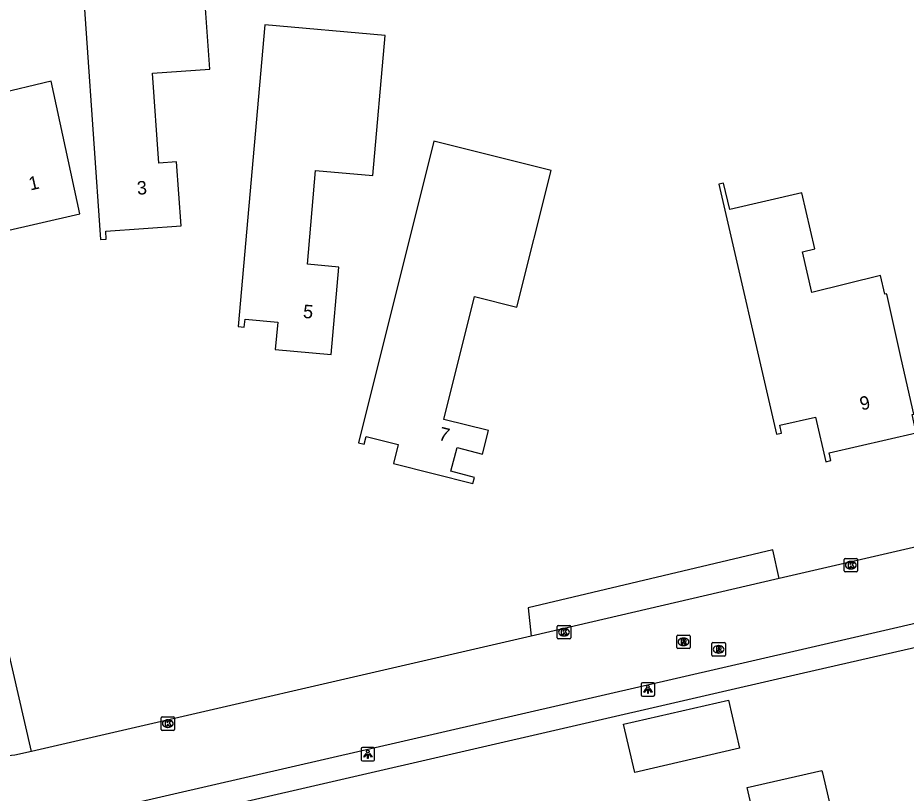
# Model space of a CAD drawing. Extents: x 156414 to 157775, y 382335 to 383765.
# Drawn here: x 156643.8 to 156709.9, y 383066 to 383123.7 of the extents above; entities that cross this region are included whole.
import ezdxf

# ---------------------------------------------------------------- set-up
doc = ezdxf.new("R2010")
doc.units = 0
for name, color, linetype in [('IMGEO_Kolk', 7, 'Continuous'), ('IMGEO_Lichtpunt', 7, 'Continuous'), ('IMGEO_Pand', 7, 'Continuous'), ('IMGEO_Pand_nummerreeks', 7, 'Continuous'), ('IMGEO_Parkeervlak_halfverhard', 7, 'Continuous'), ('IMGEO_Rijbaan_lokaal_gesloten', 7, 'Continuous'), ('IMGEO_Rioolput', 7, 'Continuous'), ('IMGEO_Voetpad_open', 7, 'Continuous')]:
    doc.layers.add(name, color=color, linetype=linetype)

msp = doc.modelspace()

# ---------------------------------------------------------------- linework, layer by layer
at = {"layer": 'IMGEO_Kolk'}
for p, q in [((156705.334, 383083.476), (156706.186, 383083.476)), ((156705.259, 383082.55), (156705.259, 383083.402)), ((156705.747, 383083.256), (156705.772, 383083.256)), ((156706.26, 383083.402), (156706.26, 383082.55)), ((156706.186, 383082.476), (156705.334, 383082.476)), ((156705.77, 383082.696), (156705.745, 383082.696)), ((156683.933, 383077.575), (156683.933, 383078.427)), ((156684.008, 383078.501), (156684.86, 383078.501)), ((156684.421, 383078.281), (156684.446, 383078.281)), ((156684.934, 383078.427), (156684.934, 383077.575)), ((156684.444, 383077.721), (156684.419, 383077.721)), ((156684.86, 383077.501), (156684.008, 383077.501)), ((156654.49, 383070.767), (156654.49, 383071.619)), ((156654.565, 383071.693), (156655.417, 383071.693)), ((156655.491, 383071.619), (156655.491, 383070.767)), ((156655.001, 383070.913), (156654.976, 383070.913)), ((156654.978, 383071.473), (156655.003, 383071.473)), ((156655.417, 383070.693), (156654.565, 383070.693))]:
    msp.add_line(p, q, dxfattribs=at)
for points in [[(156705.334, 383083.476), (156706.186, 383083.476)], [(156705.259, 383082.55), (156705.259, 383083.402)], [(156705.58, 383083.176), (156705.703, 383083.176), (156705.703, 383083.025), (156705.833, 383083.176), (156705.997, 383083.176), (156705.851, 383083.025), (156706.004, 383082.776), (156705.852, 383082.776), (156705.767, 383082.94), (156705.703, 383082.873), (156705.703, 383082.776), (156705.58, 383082.776), (156705.58, 383083.176)], [(156706.26, 383083.402), (156706.26, 383082.55)], [(156706.186, 383082.476), (156705.334, 383082.476)], [(156683.933, 383077.575), (156683.933, 383078.427)], [(156684.008, 383078.501), (156684.86, 383078.501)], [(156684.254, 383078.201), (156684.377, 383078.201), (156684.377, 383078.05), (156684.507, 383078.201), (156684.671, 383078.201), (156684.525, 383078.05), (156684.678, 383077.801), (156684.526, 383077.801), (156684.441, 383077.965), (156684.377, 383077.898), (156684.377, 383077.801), (156684.254, 383077.801), (156684.254, 383078.201)], [(156684.934, 383078.427), (156684.934, 383077.575)], [(156684.86, 383077.501), (156684.008, 383077.501)], [(156654.49, 383070.767), (156654.49, 383071.619)], [(156654.565, 383071.693), (156655.417, 383071.693)], [(156655.491, 383071.619), (156655.491, 383070.767)], [(156654.811, 383071.393), (156654.934, 383071.393), (156654.934, 383071.242), (156655.064, 383071.393), (156655.228, 383071.393), (156655.082, 383071.242), (156655.235, 383070.993), (156655.083, 383070.993), (156654.998, 383071.157), (156654.934, 383071.09), (156654.934, 383070.993), (156654.811, 383070.993), (156654.811, 383071.393)], [(156655.417, 383070.693), (156654.565, 383070.693)]]:
    msp.add_lwpolyline(points, dxfattribs=at)
for centre, start, end in [((156705.336, 383083.4), 91.55205, 178.44795), ((156705.336, 383083.4), 91.55205, 178.44795), ((156706.184, 383083.4), 1.55205, 88.44795), ((156706.184, 383083.4), 1.55205, 88.44795), ((156705.336, 383082.552), 181.55205, 268.44795), ((156705.336, 383082.552), 181.55205, 268.44795), ((156706.184, 383082.552), 271.55205, 358.44795), ((156706.184, 383082.552), 271.55205, 358.44795), ((156684.01, 383078.425), 91.55205, 178.44795), ((156684.01, 383078.425), 91.55205, 178.44795), ((156684.858, 383078.425), 1.55205, 88.44795), ((156684.858, 383078.425), 1.55205, 88.44795), ((156684.01, 383077.577), 181.55205, 268.44795), ((156684.01, 383077.577), 181.55205, 268.44795), ((156684.858, 383077.577), 271.55205, 358.44795), ((156684.858, 383077.577), 271.55205, 358.44795), ((156654.567, 383071.617), 91.55205, 178.44795), ((156654.567, 383071.617), 91.55205, 178.44795), ((156655.415, 383071.617), 1.55205, 88.44795), ((156655.415, 383071.617), 1.55205, 88.44795), ((156654.567, 383070.769), 181.55205, 268.44795), ((156654.567, 383070.769), 181.55205, 268.44795), ((156655.415, 383070.769), 271.55205, 358.44795), ((156655.415, 383070.769), 271.55205, 358.44795)]:
    msp.add_arc(centre, 0.0765, start, end, dxfattribs=at)
for centre, major_axis, ratio, start_param, end_param in [((156705.746, 383082.976), (-0.387, 0.002), 0.722429, 4.712389, 7.853982), ((156705.771, 383082.976), (-0.39, 0.002), 0.717154, 1.570796, 4.712389), ((156684.42, 383078.001), (-0.387, 0.002), 0.722429, 4.712389, 7.853982), ((156684.445, 383078.001), (-0.39, 0.002), 0.717154, 1.570796, 4.712389), ((156654.977, 383071.193), (-0.387, 0.002), 0.722429, 4.712389, 7.853982), ((156655.002, 383071.193), (-0.39, 0.002), 0.717154, 1.570796, 4.712389)]:
    msp.add_ellipse(centre, major_axis=major_axis, ratio=ratio, start_param=start_param, end_param=end_param, dxfattribs=at)
at = {"layer": 'IMGEO_Lichtpunt'}
for p, q in [((156691.084, 383074.226), (156690.276, 383074.226)), ((156691.084, 383074.226), (156690.276, 383074.226)), ((156690.182, 383074.131), (156690.182, 383073.324)), ((156690.182, 383074.131), (156690.182, 383073.324)), ((156691.178, 383073.324), (156691.178, 383074.131)), ((156691.178, 383073.324), (156691.178, 383074.131)), ((156690.276, 383073.23), (156691.084, 383073.23)), ((156690.276, 383073.23), (156691.084, 383073.23)), ((156669.364, 383069.317), (156669.364, 383068.51)), ((156669.364, 383069.317), (156669.364, 383068.51)), ((156670.266, 383069.412), (156669.458, 383069.412)), ((156670.266, 383069.412), (156669.458, 383069.412)), ((156670.36, 383068.51), (156670.36, 383069.317)), ((156670.36, 383068.51), (156670.36, 383069.317)), ((156669.458, 383068.416), (156670.266, 383068.416)), ((156669.458, 383068.416), (156670.266, 383068.416))]:
    msp.add_line(p, q, dxfattribs=at)
for points in [[(156690.556, 383073.795), (156690.595, 383073.767), (156690.407, 383073.505), (156690.369, 383073.532), (156690.556, 383073.795)], [(156690.658, 383073.747), (156690.705, 383073.747), (156690.705, 383073.425), (156690.658, 383073.425), (156690.658, 383073.747)], [(156690.768, 383073.767), (156690.806, 383073.794), (156690.993, 383073.532), (156690.954, 383073.504), (156690.768, 383073.767)], [(156669.738, 383068.981), (156669.777, 383068.953), (156669.589, 383068.691), (156669.551, 383068.718), (156669.738, 383068.981)], [(156669.84, 383068.933), (156669.887, 383068.933), (156669.887, 383068.611), (156669.84, 383068.611), (156669.84, 383068.933)], [(156669.95, 383068.953), (156669.988, 383068.98), (156670.175, 383068.718), (156670.136, 383068.69), (156669.95, 383068.953)]]:
    msp.add_lwpolyline(points, dxfattribs=at)
for centre in [(156690.681, 383073.929), (156669.863, 383069.115)]:
    msp.add_circle(centre, 0.0994, dxfattribs=at)
for centre, start, end in [((156690.276, 383074.131), 90, 180), ((156690.276, 383074.131), 90, 180), ((156691.084, 383074.131), 0, 90), ((156691.084, 383074.131), 0, 90), ((156690.276, 383073.324), 180, 270), ((156690.276, 383073.324), 180, 270), ((156691.084, 383073.324), 270, 0), ((156691.084, 383073.324), 270, 360), ((156669.458, 383069.317), 90, 180), ((156669.458, 383069.317), 90, 180), ((156670.266, 383069.317), 0, 90), ((156670.266, 383069.317), 0, 90), ((156669.458, 383068.51), 180, 270), ((156669.458, 383068.51), 180, 270), ((156670.266, 383068.51), 270, 0), ((156670.266, 383068.51), 270, 360)]:
    msp.add_arc(centre, 0.0946, start, end, dxfattribs=at)
at = {"layer": 'IMGEO_Pand'}
for points in [[(156642.53, 383107.745), (156648.455, 383109.102), (156646.309, 383118.979), (156642.145, 383117.991), (156640.536, 383124.773), (156644.7, 383125.761), (156642.276, 383135.977), (156633.494, 383133.894), (156639.379, 383108.522), (156639.808, 383108.61), (156639.688, 383109.197), (156642.07, 383109.742), (156642.53, 383107.745)], [(156655.97, 383108.231), (156655.639, 383112.983), (156654.312, 383112.891), (156653.845, 383119.584), (156658.105, 383119.882), (156657.377, 383130.306), (156648.432, 383129.682), (156649.988, 383107.211), (156650.412, 383107.235), (156650.377, 383107.834), (156655.97, 383108.231)], [(156667.131, 383098.658), (156667.7, 383105.147), (156665.361, 383105.374), (156665.97, 383112.327), (156670.238, 383111.957), (156671.14, 383122.377), (156662.195, 383123.17), (156660.227, 383100.743), (156660.658, 383100.684), (156660.739, 383101.279), (156663.154, 383101.064), (156662.972, 383099.03), (156667.131, 383098.658)], [(156677.67, 383089.063), (156677.789, 383089.499), (156676.034, 383089.979), (156676.494, 383091.736), (156678.388, 383091.234), (156678.825, 383092.996), (156675.501, 383093.825), (156677.779, 383102.955), (156680.932, 383102.168), (156683.481, 383112.335), (156674.761, 383114.516), (156669.16, 383092.072), (156669.582, 383091.968), (156669.724, 383092.551), (156672.119, 383091.95), (156671.766, 383090.539), (156677.67, 383089.063)], [(156709.503, 383098.344), (156708.449, 383103.028), (156708.413, 383103.174), (156708.296, 383103.145), (156707.953, 383104.533), (156702.857, 383103.273), (156702.16, 383106.294), (156703.076, 383106.505), (156702.116, 383110.671), (156696.77, 383109.433), (156696.302, 383111.384), (156695.95, 383111.311), (156700.223, 383092.713), (156700.601, 383092.796), (156700.472, 383093.382), (156703.125, 383093.982), (156703.898, 383090.668), (156704.271, 383090.754), (156704.137, 383091.339), (156710.627, 383092.83), (156710.315, 383094.185), (156710.432, 383094.212), (156709.503, 383098.344)], [(156689.692, 383067.547), (156688.86, 383071.148), (156696.654, 383072.935), (156697.494, 383069.356), (156689.692, 383067.547)], [(156702.019, 383054.701), (156696.71, 383056.789), (156698.974, 383062.447), (156698.06, 383066.446), (156703.613, 383067.714), (156703.653, 383067.543), (156704.948, 383061.996), (156702.019, 383054.701)]]:
    msp.add_lwpolyline(points, dxfattribs=at)
at = {"layer": 'IMGEO_Parkeervlak_halfverhard'}
msp.add_lwpolyline([(156700.442, 383081.982), (156699.964, 383084.108), (156681.774, 383079.815), (156681.985, 383077.701)], dxfattribs=at)
at = {"layer": 'IMGEO_Rijbaan_lokaal_gesloten'}
for points in [[(156646.397, 383063.893), (156701.856, 383076.667), (156794.235, 383098.006), (156794.644, 383096.091)], [(156754.754, 383094.533), (156700.442, 383081.982)], [(156700.442, 383081.982), (156681.985, 383077.701)], [(156681.985, 383077.701), (156644.854, 383069.113)], [(156644.854, 383069.113), (156643.605, 383068.842), (156642.876, 383068.782)]]:
    msp.add_lwpolyline(points, dxfattribs=at)
at = {"layer": 'IMGEO_Rioolput'}
for p, q in [((156692.822, 383076.852), (156692.822, 383077.704)), ((156692.897, 383077.778), (156693.749, 383077.778)), ((156693.31, 383077.558), (156693.335, 383077.558)), ((156693.823, 383077.704), (156693.823, 383076.852)), ((156693.333, 383076.998), (156693.308, 383076.998)), ((156695.43, 383076.293), (156695.43, 383077.145)), ((156695.505, 383077.219), (156696.357, 383077.219)), ((156695.918, 383076.999), (156695.943, 383076.999)), ((156696.431, 383077.145), (156696.431, 383076.293)), ((156693.749, 383076.778), (156692.897, 383076.778)), ((156696.357, 383076.219), (156695.505, 383076.219)), ((156695.941, 383076.439), (156695.916, 383076.439))]:
    msp.add_line(p, q, dxfattribs=at)
for points in [[(156692.822, 383076.852), (156692.822, 383077.704)], [(156692.897, 383077.778), (156693.749, 383077.778)], [(156693.823, 383077.704), (156693.823, 383076.852)], [(156693.411, 383077.476), (156693.159, 383077.478), (156693.159, 383077.078)], [(156693.159, 383077.078), (156693.283, 383077.078), (156693.283, 383077.24), (156693.294, 383077.24)], [(156693.337, 383077.397), (156693.283, 383077.397), (156693.283, 383077.316)], [(156693.283, 383077.316), (156693.335, 383077.316)], [(156693.341, 383077.211), (156693.412, 383077.078), (156693.552, 383077.078), (156693.487, 383077.204)], [(156695.43, 383076.293), (156695.43, 383077.145)], [(156695.505, 383077.219), (156696.357, 383077.219)], [(156696.019, 383076.917), (156695.767, 383076.919), (156695.767, 383076.519)], [(156696.431, 383077.145), (156696.431, 383076.293)], [(156693.749, 383076.778), (156692.897, 383076.778)], [(156696.357, 383076.219), (156695.505, 383076.219)], [(156695.767, 383076.519), (156695.891, 383076.519), (156695.891, 383076.681), (156695.902, 383076.681)], [(156695.945, 383076.838), (156695.891, 383076.838), (156695.891, 383076.757)], [(156695.891, 383076.757), (156695.943, 383076.757)], [(156695.949, 383076.652), (156696.02, 383076.519), (156696.16, 383076.519), (156696.095, 383076.645)]]:
    msp.add_lwpolyline(points, dxfattribs=at)
for centre, radius, start, end in [((156692.899, 383077.702), 0.0765, 91.55205, 178.44795), ((156692.899, 383077.702), 0.0765, 91.55205, 178.44795), ((156693.747, 383077.702), 0.0765, 1.55205, 88.44795), ((156693.747, 383077.702), 0.0765, 1.55205, 88.44795), ((156692.899, 383076.854), 0.0765, 181.55205, 268.44795), ((156692.899, 383076.854), 0.0765, 181.55205, 268.44795), ((156693.293, 383077.187), 0.0533, 26.02933, 88.69889), ((156693.319, 383077.505), 0.19, 274.7715, 282.96867), ((156693.343, 383077.301), 0.0964, 77.00612, 93.18647), ((156693.357, 383077.358), 0.0378, 276.66336, 79.67722), ((156693.41, 383077.366), 0.109, 350.36119, 89.41601), ((156693.408, 383077.366), 0.112, 277.58423, 350.98172), ((156693.392, 383077.151), 0.108, 29.51342, 73.79051), ((156693.747, 383076.854), 0.0765, 271.55205, 358.44795), ((156693.747, 383076.854), 0.0765, 271.55205, 358.44795), ((156695.507, 383077.143), 0.0765, 91.55205, 178.44795), ((156695.507, 383077.143), 0.0765, 91.55205, 178.44795), ((156696.018, 383076.807), 0.109, 350.36119, 89.41601), ((156696.355, 383077.143), 0.0765, 1.55205, 88.44795), ((156696.355, 383077.143), 0.0765, 1.55205, 88.44795), ((156695.507, 383076.295), 0.0765, 181.55205, 268.44795), ((156695.507, 383076.295), 0.0765, 181.55205, 268.44795), ((156695.901, 383076.628), 0.0533, 26.02933, 88.69889), ((156695.927, 383076.946), 0.19, 274.7715, 282.96867), ((156695.951, 383076.742), 0.0964, 77.00612, 93.18647), ((156695.965, 383076.799), 0.0378, 276.66336, 79.67722), ((156696.016, 383076.807), 0.112, 277.58423, 350.98172), ((156696, 383076.592), 0.108, 29.51342, 73.79051), ((156696.355, 383076.295), 0.0765, 271.55205, 358.44795), ((156696.355, 383076.295), 0.0765, 271.55205, 358.44795)]:
    msp.add_arc(centre, radius, start, end, dxfattribs=at)
for centre, major_axis, ratio, start_param, end_param in [((156693.309, 383077.278), (-0.387, 0.002), 0.722429, 4.712389, 7.853982), ((156693.334, 383077.278), (-0.39, 0.002), 0.717154, 1.570796, 4.712389), ((156695.917, 383076.719), (-0.387, 0.002), 0.722429, 4.712389, 7.853982), ((156695.942, 383076.719), (-0.39, 0.002), 0.717154, 1.570796, 4.712389)]:
    msp.add_ellipse(centre, major_axis=major_axis, ratio=ratio, start_param=start_param, end_param=end_param, dxfattribs=at)
at = {"layer": 'IMGEO_Voetpad_open'}
for points in [[(156644.854, 383069.113), (156631.483, 383127.286), (156624.81, 383156.005)], [(156650.985, 383063.152), (156702.248, 383074.98), (156794.644, 383096.091)]]:
    msp.add_lwpolyline(points, dxfattribs=at)

# ---------------------------------------------------------------- texts
at = {"layer": 'IMGEO_Pand_nummerreeks'}
for s, rotation, p in [('1', 12.89906, (156644.772, 383110.844)), ('3', 4.05673, (156652.724, 383110.527)), ('5', 354.88895, (156665.006, 383101.379)), ('9', 12.9462, (156706.549, 383094.479)), ('7', 345.9635, (156675.065, 383092.312))]:
    msp.add_text(s, height=1, rotation=rotation, dxfattribs=at).set_placement(p)

doc.saveas('drawing.dxf')
